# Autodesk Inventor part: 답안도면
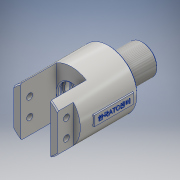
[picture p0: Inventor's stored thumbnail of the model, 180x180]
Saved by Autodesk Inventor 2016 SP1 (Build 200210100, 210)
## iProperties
Created: 2019-02
Part Number: 답안도면
Material: 알루미늄 6061
Document SubType Name: Modeling
Designer: basic
Density: 2.7 g/cm^3
Appearance: 알루미늄 - 평지
Mass: 345.889 g
Surface Area: 290.427 cm^2
Volume: 128.107 cm^3
Author: basic
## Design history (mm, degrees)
sketch "스케치1"
  geometry: L1 (-54, 0)-(54, 0); L2 (-54, 0)-(-54, 29); L3 (20, 29)-(20, 13); L4 (20, 13)-(25, 13); L5 (25, 13)-(25, 15); L6 (25, 15)-(54, 15); L7 (54, 15)-(54, 0); L8 (-54, 29)-(20, 29); 2 further points
  constraints: 16 end point, 5 perpendicular, 1 coincident, 1 horizontal, 1 midpoint, 1 vertical
  dimensions: "d0" = 108 distance of L1.start L1.end; "d2" = 74 distance between parallel lines of L2 L3; "d3" = 26 diameter of L4 L1; "d4" = 58 diameter of L8 L1; "d5" = 30 diameter of L6 L1; "d6" = 5 distance of L3.end L4.end
revolve "회전1" sketch "스케치1" stored, may be unused: angle "d7" = 90 deg
sketch "스케치2"
  geometry: L1 (29, -54)-(-29, -54) reference; L2 (-15, -54)-(-15, -18); L3 (-15, -18)-(15, -18); L4 (15, -18)-(15, -54); L5 (-15, -54)-(15, -54); 2 further points
  constraints: 8 end point, 2 perpendicular, 2 point on line, 1 collinear, 1 midpoint, 1 vertical, 1 vertical alignment
  dimensions: "d8" = 30 distance of L2.end L3.end; "d9" = 36 distance of L2.start L2.end
extrude "돌출1" cut sketch "스케치2" stored distance "d10" = 10; taper "d11" = 0 deg
sketch "스케치3"
  geometry: L1 (-18, -24.819)-(-18, 24.819) reference; L2 (-18, 14)-(-15.35, 14); L3 (-15.35, 14)-(-15.35, 17); L4 (-15.35, 17)-(-10.65, 17); L5 (-10.65, 17)-(-10.65, 14); L6 (-18, 0)-(54, 0); L7 (54, -15)-(54, 15) reference; L8 (-10.65, 14)-(-6.35, 14); L9 (-6.35, 14)-(-6.35, 17); L10 (-6.35, 17)-(-1.65, 17); L11 (-1.65, 17)-(-1.65, 14); L12 (-1.65, 14)-(2, 14); L13 (2, 14)-(2, 16); L14 (2, 16)-(9, 16); L15 (9, 16)-(9, 0); L16 (-18, 14)-(-18, 0); 1 further point
  constraints: 28 end point, 10 perpendicular, 5 point on line, 2 horizontal, 2 midpoint, 1 collinear
  dimensions: "d12" = 4.7 distance of L3.end L4.end; "d13" = 7 distance of L13.end L14.end; "d14" = 32 diameter of L14 L6; "d16" = 28 diameter of L2 L6; "d17" = 34 diameter of L4 L6; "d18" = 34 diameter of L10 L6; "d20" = 4.3 distance between parallel lines of L9 L5; "d21" = 2.65 distance between parallel lines of L1 L3; "d22" = 20 distance between parallel lines of L13 L1
sketch "스케치4"
  geometry: L1 (29, -54)-(15, -54) reference; L2 (22, -54)-(22, -38); L3 (22, -38)-(29, -38); L4 (29, -54)-(29, 20) reference; L5 (22, -54)-(29, -54); 1 further point
  constraints: 6 end point, 2 perpendicular, 1 collinear, 1 midpoint, 1 point on line
  dimensions: "d28" = 16 distance of L2.start L2.end; "d29" = 22 distance from line of point (0, 0) L2
extrude "돌출2" cut sketch "스케치4" stored distance "d30" = 10; taper "d31" = 0 deg
sketch "스케치5"
  geometry: L1 (-43.714, 0)-(5.925, 0) reference; 2 further points
  dimensions: "d32" = 9 distance from line of L1 point (-27.894, 9); "d33" = 9 horizontal distance of point (-27.894, 9) point (-18.894, 54)
hole "구멍1" sketch "스케치5" at (-27.894, 9) diameter "d34" = 6; stored, may be unused: countersink angle "d38" = 90 deg, drill point angle "d40" = 0 deg; dims "d35" = 6, "d36" = 4, "d37" = 2, "d39" = 8
feature "스레드1" dims "d41" = 10, "d42" = 0
node "작업 평면1"
sketch "스케치6"
  geometry: L1 (-25, 5)-(15, 5); L2 (15, 5)-(15, -5); L3 (15, -5)-(-25, -5); L4 (-25, -5)-(-25, 5); L5 (-25, 5)-(15, -5); L6 (15, 5)-(-25, -5); L7 (20, -29)-(20, 29) reference; 3 further points
  constraints: 12 end point, 3 midpoint, 2 parallel, 1 horizontal, 1 horizontal alignment, 1 perpendicular
  dimensions: "d53" = 40 distance of L1.start L1.end; "d54" = 10 distance of L1.end L2.end; "d55" = 5 distance between parallel lines of L7 L2
extrude "돌출3" join sketch "스케치6" stored distance "d56" = 10; taper "d57" = 0 deg
sketch "스케치7"
  geometry: L1 (5, -25)-(-5, -25) reference; L2 (5, 15)-(5, -25) reference; 2 further points
  constraints: 1 other
  dimensions: "d58" = 20 distance from line of L1 point (0, -5); "d59" = 5 distance from line of L2 point (0, -5)
feature "엠보싱1" sketch "스케치7" dims "d60" = 0.5, "d61" = 0
chamfer "모따기1" distance "d62" = 1; stored, may be unused: second distance "d63" = 2, angle "d64" = 45 deg
revolve "회전3" stored, may be unused: angle "d78" = 90 deg
hole "구멍3" diameter "d81" = 8; stored, may be unused: countersink angle "d85" = 90 deg, drill point angle "d87" = 0 deg; dims "d79" = 10, "d80" = 10, "d82" = 28, "d83" = 4, "d84" = 2, "d86" = 18
hole "구멍4" diameter "d90" = 12.376; stored, may be unused: countersink angle "d94" = 90 deg, drill point angle "d96" = 118 deg; dims "d88" = 10, "d89" = 10, "d91" = 18, "d92" = 4, "d93" = 2, "d95" = 22
fillet "모깎기2" dims "d97" = 0.8
chamfer "모따기4" distance "d98" = 1; stored, may be unused: second distance "d99" = 2, angle "d100" = 45 deg
node "솔리드1"
mirror "대칭1"
mirror "대칭2"
